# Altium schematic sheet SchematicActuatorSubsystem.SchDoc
size A
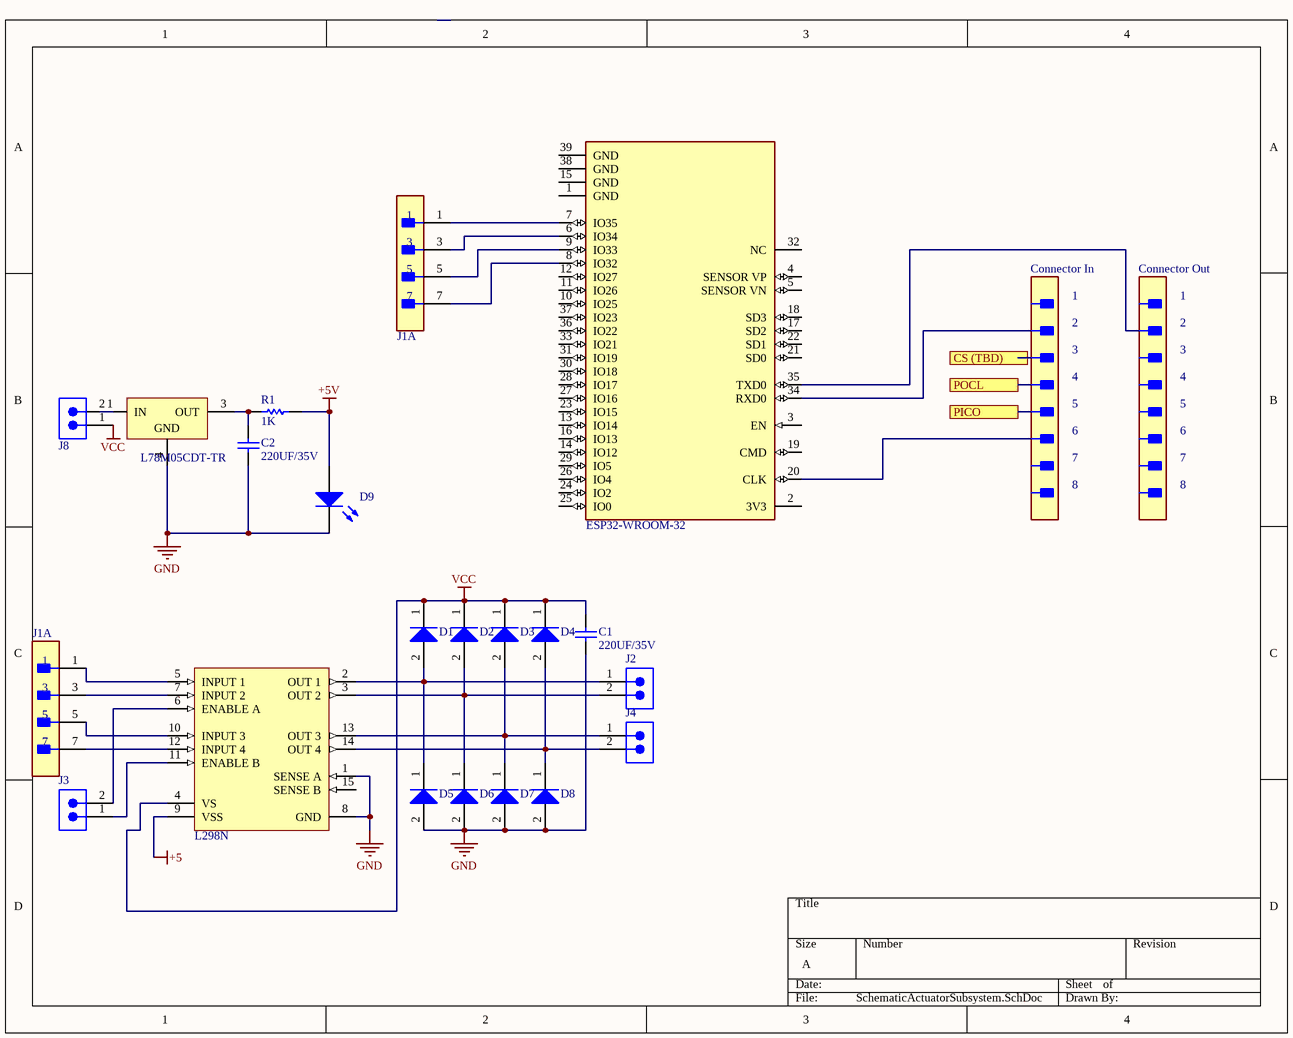
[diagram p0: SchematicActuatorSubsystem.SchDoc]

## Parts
(Parts that share a designator on the sheet are numbered #1, #2 ... from top to bottom, then left to right.)
?  L298N  [STM-FM-15]
C1  value 220UF/35V  (hidden comment: Capacitor)
C2  value 220UF/35V  (hidden comment: Capacitor)
Connector_In  39-01-2081  [FP-39-01-2081-MFG]  (value not drawn)
Connector_Out  39-01-2081  [FP-39-01-2081-MFG]  (value not drawn)
D1  BAT54HT1G  [ONSC-SOD-323-2-477-02_V]  (value not drawn)
D2  BAT54HT1G  [ONSC-SOD-323-2-477-02_V]  (value not drawn)
D3  BAT54HT1G  [ONSC-SOD-323-2-477-02_V]  (value not drawn)
D4  BAT54HT1G  [ONSC-SOD-323-2-477-02_V]  (value not drawn)
D5  BAT54HT1G  [ONSC-SOD-323-2-477-02_V]  (value not drawn)
D6  BAT54HT1G  [ONSC-SOD-323-2-477-02_V]  (value not drawn)
D7  BAT54HT1G  [ONSC-SOD-323-2-477-02_V]  (value not drawn)
D8  BAT54HT1G  [ONSC-SOD-323-2-477-02_V]  (value not drawn)
D9  Light-Emitting Diode  (value not drawn)
J1#1  87831-0841  [FP-87831-0841-MFG]  (value not drawn)  (part A of 2)
J1#2  87831-0841  [FP-87831-0841-MFG]  (value not drawn)  (part A of 2)
J2  620302124022  [620302124022]  (value not drawn)
J3  620302124022  [620302124022]  (value not drawn)
J4  620302124022  [620302124022]  (value not drawn)
J8  620302124022  [620302124022]  (value not drawn)
MD?  ESP32-WROOM-32  [FP-ESP32-WROOM-32-MFG]
R1  value 1K  (hidden comment: Resistor)
U?  L78M05CDT-TR  [TO-252_L]

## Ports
CS (TBD), PICO, POCL

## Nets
+5: ?.9(VSS)
+5V: D9.1(A) R1.2
GND: ?.1(SENSE_A) ?.8(GND) C1.2 C2.1 D5.2(A) D6.2(A) D7.2(A) D8.2(A) D9.2(K) U?.4(GND)
VCC: ?.4(VS) C1.1 D1.1(K) D2.1(K) D3.1(K) D4.1(K) J8.1
Net?_2: ?.2(OUT_1) D1.2(A) D5.1(K) J2.1
Net?_3: ?.3(OUT_2) D2.2(A) D6.1(K) J2.2
Net?_5: ?.5(INPUT_1) J1#2.1
Net?_6: ?.6(ENABLE_A) J3.2
Net?_7: ?.7(INPUT_2) J1#2.3
Net?_10: ?.10(INPUT_3) J1#2.5
Net?_11: ?.11(ENABLE_B) J3.1
Net?_12: ?.12(INPUT_4) J1#2.7
Net?_13: ?.13(OUT_3) D3.2(A) D7.1(K) J4.1
Net?_14: ?.14(OUT_4) D4.2(A) D8.1(K) J4.2
NetC2_2: C2.2 R1.1 U?.3(OUT)
NetJ1#1_1: J1#1.1 MD?.7(IO35)
NetJ1#1_3: J1#1.3 MD?.6(IO34)
NetJ1#1_5: J1#1.5 MD?.9(IO33)
NetJ1#1_7: J1#1.7 MD?.8(IO32)
NetJ8_2: J8.2 U?.1(IN)

Not connected (* = marked no-connect by the designer): ? 15(SENSE_B); MD? 1(GND) 2(3V3) 3(EN) 4(SENSOR_VP) 5(SENSOR_VN) 10(IO25) 11(IO26) 12(IO27) 13(IO14) 14(IO12) 15(GND) 16(IO13) 17(SD2) 18(SD3) 19(CMD) 20(CLK) 21(SD0) 22(SD1) 23(IO15) 24(IO2) 25(IO0) 26(IO4) 27(IO16) 28(IO17) 29(IO5) 30(IO18) 31(IO19) 32(NC) 33(IO21) 34(RXD0) 35(TXD0) 36(IO22) 37(IO23) 38(GND) 39(GND)

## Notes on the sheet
- 1
- 2
- (near Connector_In) 3
- (near Connector_In) 4
- (near Connector_Out) 3
- (near Connector_Out) 4
- (near Connector_In) 5
- (near Connector_In) 6
- (near Connector_Out) 5
- (near Connector_Out) 6
- 7
- 8

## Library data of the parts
? = CMP-2000-06526-1: Dual Full-Bridge Driver, 4.8 to 46 V, -40 to 150 degC, 15-Pin FM (MW 15L), RoHS, Tube; Manufacturer: STMicroelectronics; PartNumber: L298; Output Current: 2A; Supply Voltage Max: 7V; Driver Case Style: Multiwatt; Supply Voltage Min: 4.5V; No. of Pins: 15Pins; SVHC: NoSVHC(17-Dec-2015); Output Voltage: 46V; No. of Outputs: 4Outputs; Motor Type: FullBridge
C1 C2 = Capacitor: SimulationGenericComponent: True
Connector_In Connector_Out = CMP-04776-000197-1: CONN PLUG 8POS PANEL MOUNT; Max Voltage Rating (AC): 600V; Pitch: 4.2mm; Number of Positions: 8; Row Spacing: 0.165inch
D1-D8 = CMP-1055-00462-1: Schottky Barrier Diode, 2-Pin SOD-323, Pb-Free, Tape and Reel; Manufacturer: On Semiconductor; Configuration: Single; trr Max (ns): 5; IFSM Max (A): 0.6
D9 = LED: AF: 1; BV: 0; BV_MAX: 1e99; EG: 1.11; FC: 0.5; IBV: 0.001; IS: 1e-14; MJSW: 0.33; NTUN: 30; TNOM: 27; XTI: 3; SimulationGenericComponent: True
J1#1 J1#2 = CMP-04776-000334-1: CONN HEADER VERT 8POS 2MM; Glow Wire Compliant: Non-compliant; Number of Positions: 8; Voltage Rating: 125V; Current Rating: 2A
J2-J4 J8 = CMP-1502-00660-2: NexarPartId: 18818242; Insulation: Insulated; Connector Type: Male Pin; Pitch: 2mm; Insulation Resistance: 1GΩ; Gender: Male; Voltage Rating: 125V; Number of Positions: 2; Contact Resistance: 20mΩ; Operating Supply Voltage: 100V; Current Rating: 2A
MD? = CMP-194065-000008-1: RX TXRX MOD WIFI SURFACE MOUNT; Frequency: 2.5GHz; Sensitivity: -98dBm; Operating Supply Voltage: 3.6V; Data Rate: 150Mbps
R1 = Resistor: TC1: 0; SimulationGenericComponent: True
U? = CMP-0244-00178-1: Positive Voltage Regulator, 5V, 3-Pin DPAK, Tape and Reel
